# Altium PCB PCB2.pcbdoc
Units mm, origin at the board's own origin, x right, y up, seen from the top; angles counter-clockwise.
Board outline 219.08 x 148.92 mm, 2 copper layers (Top Layer, Bottom Layer); 86 components, 96 nets, 400 pads, 0 vias.
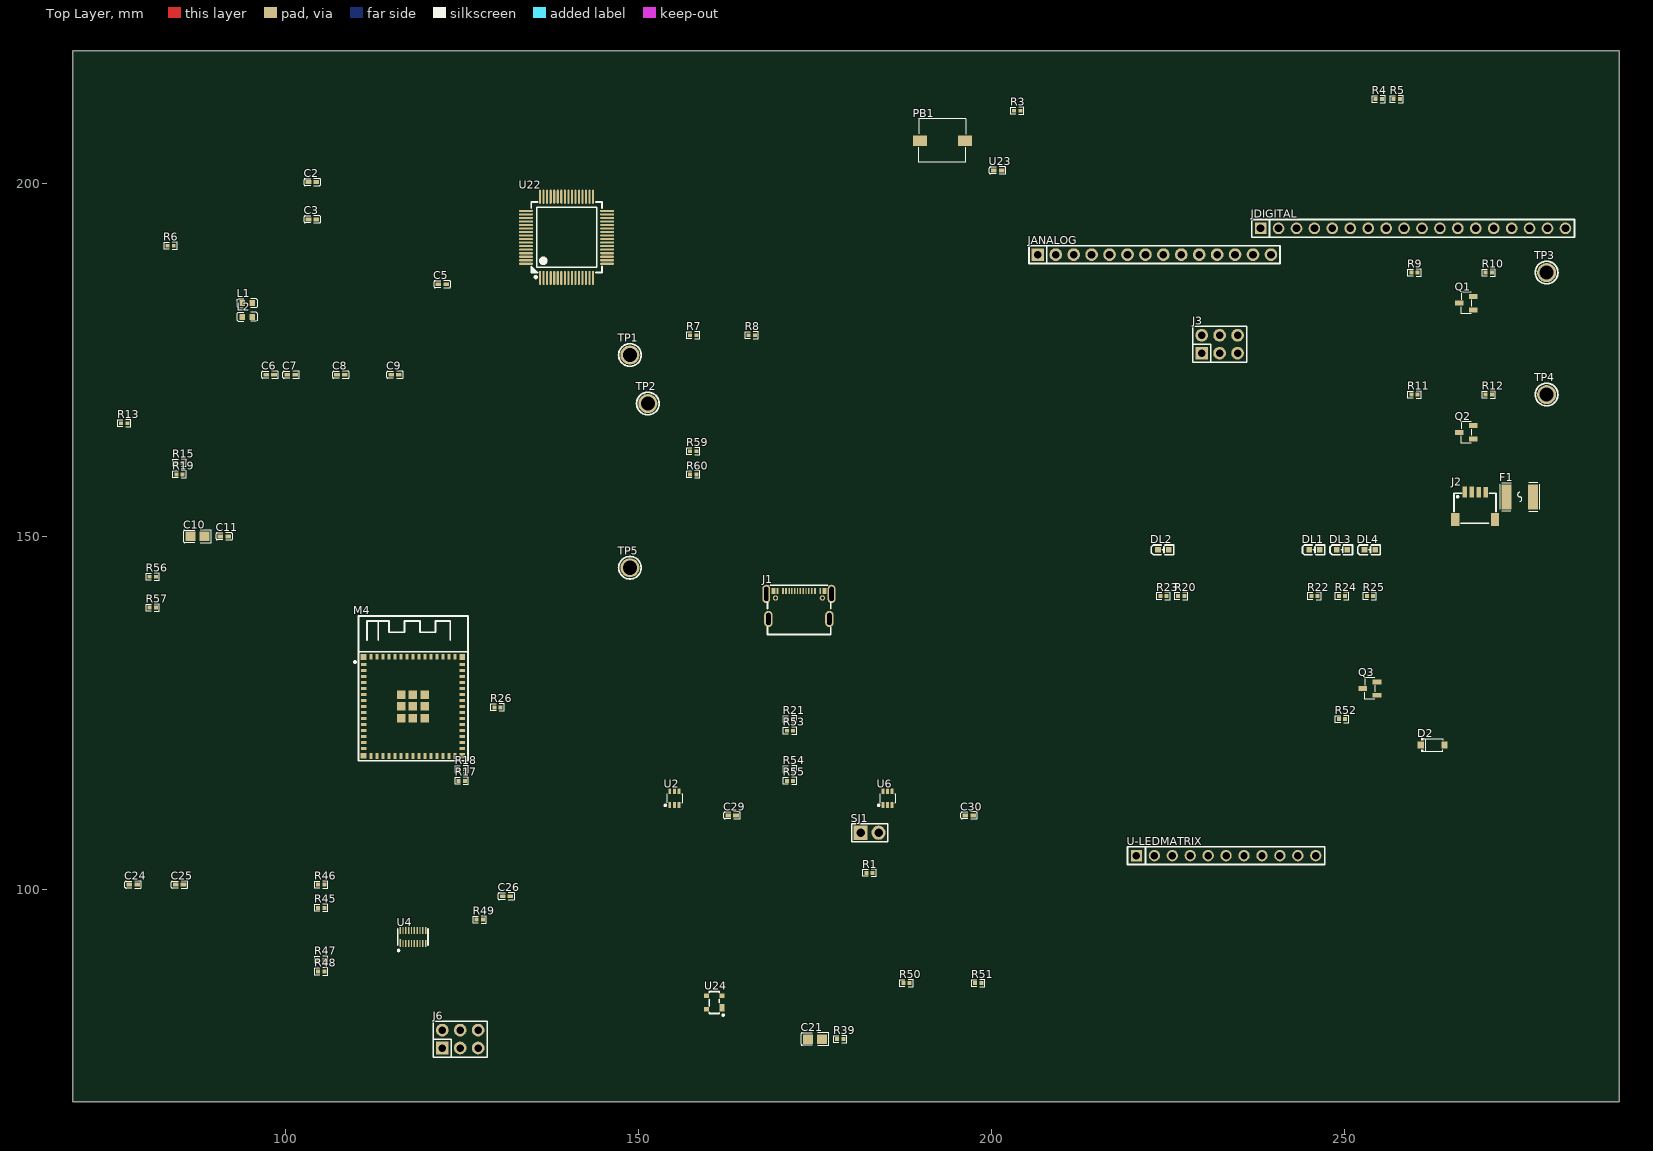
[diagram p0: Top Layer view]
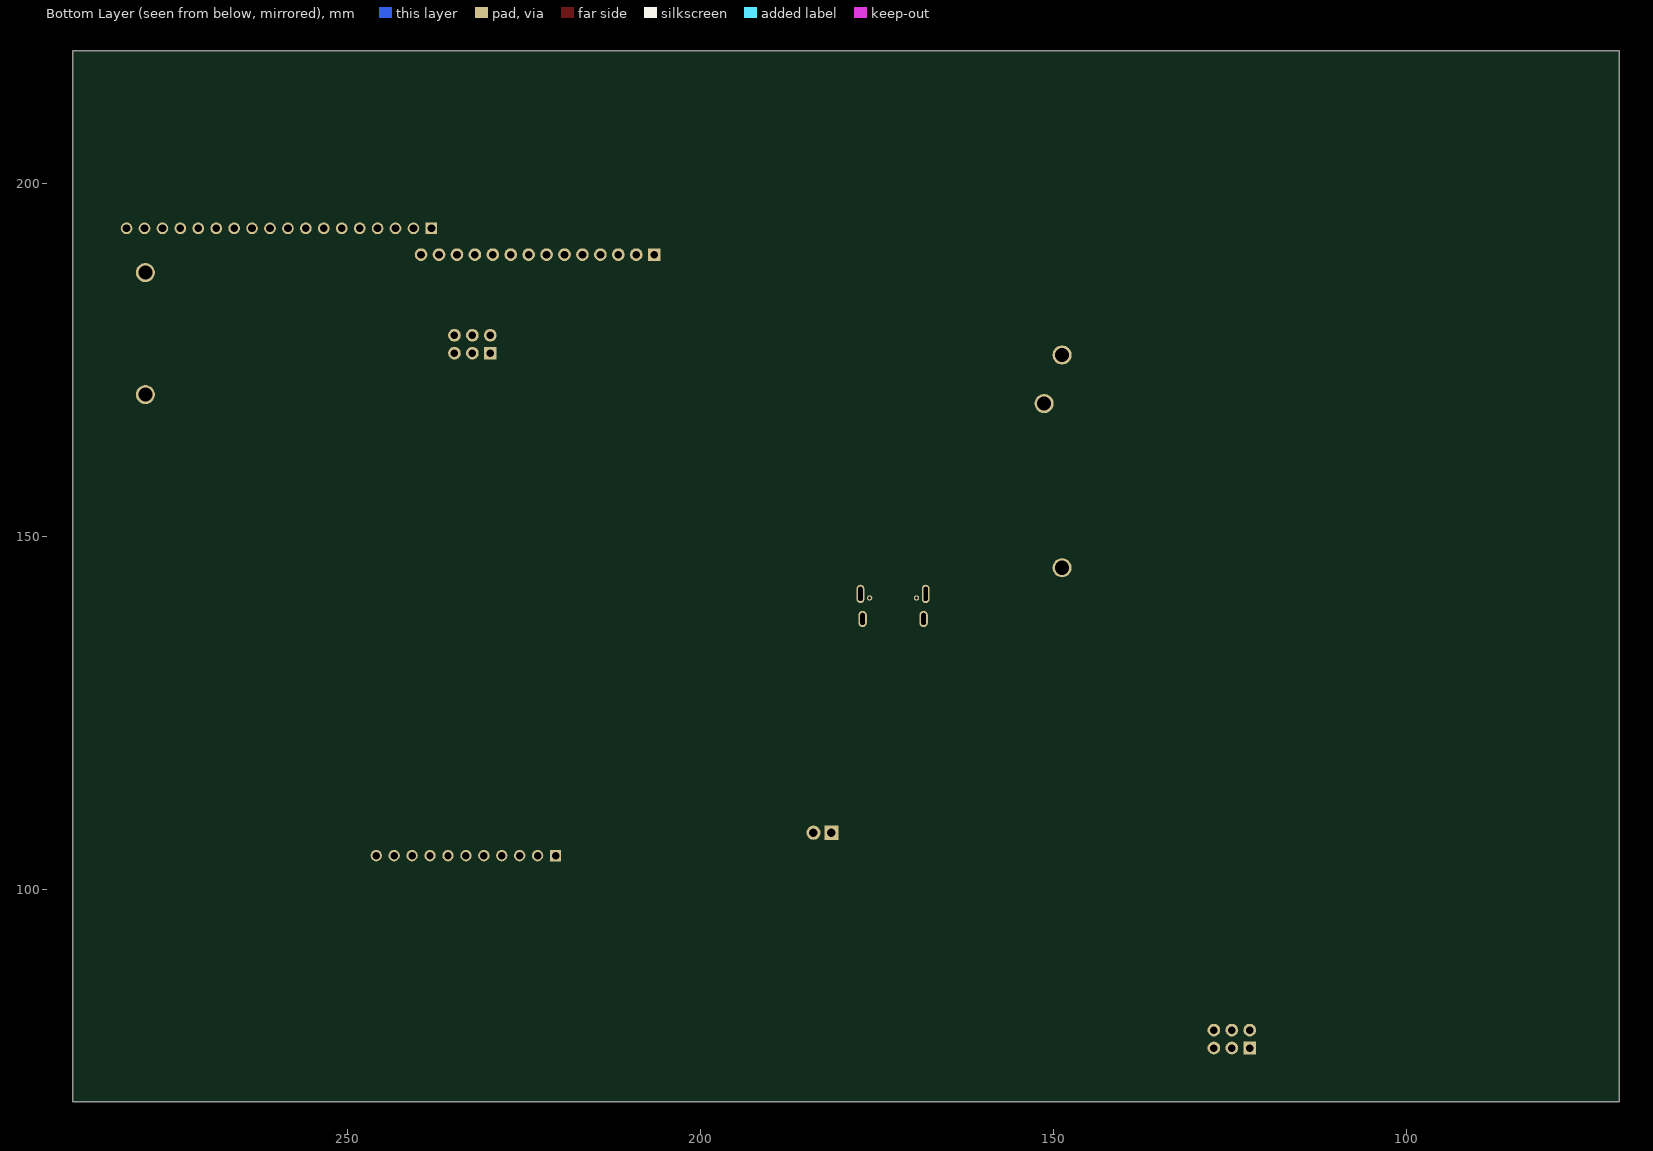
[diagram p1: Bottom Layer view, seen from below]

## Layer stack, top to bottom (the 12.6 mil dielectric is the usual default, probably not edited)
Top Layer: signal copper (thickness not stored)
Dielectric: dielectric 0.32, FR-4, Dk 4.8
Bottom Layer: signal copper (thickness not stored)

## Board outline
288.927,69.85 69.85,69.85 69.85,218.768 288.927,218.768

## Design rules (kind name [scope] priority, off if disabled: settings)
BoardOutlineClearance copperThickness1oz [All] p0: genericclearance=0.254 ignorepadtopadclearanceinfootprint=FALSE except(0: Arc-SplitContinuation Track-SplitContinuation SMDPad-SplitContinuation THPad-SplitContinuation Via-SplitContinuation Fill-SplitContinuation Poly-SplitContinuation Region-SplitContinuation Text-SplitContinuation; 0.152: Track-CutoutEdge SMDPad-CutoutEdge THPad-CutoutEdge Via-CutoutEdge Region-CutoutEdge; 0.3: Track-OutlineEdge SMDPad-OutlineEdge THPad-OutlineEdge Via-OutlineEdge Fill-OutlineEdge Region-OutlineEdge Poly-OutlineEdge Text-OutlineEdge Fill-CutoutEdge)
BoardOutlineClearance copperThickness2oz [All] p0: genericclearance=0.254 ignorepadtopadclearanceinfootprint=FALSE except(0: Arc-SplitContinuation Track-SplitContinuation SMDPad-SplitContinuation THPad-SplitContinuation Via-SplitContinuation Fill-SplitContinuation Poly-SplitContinuation Region-SplitContinuation Text-SplitContinuation; 0.152: Track-CutoutEdge SMDPad-CutoutEdge THPad-CutoutEdge Via-CutoutEdge Region-CutoutEdge; 0.3: Track-OutlineEdge SMDPad-OutlineEdge THPad-OutlineEdge Via-OutlineEdge Fill-OutlineEdge Region-OutlineEdge Poly-OutlineEdge Text-OutlineEdge Fill-CutoutEdge)
Clearance copperThickness1oz [(InNet('+4V5') OR InNet('GND') OR InNet('$1N538') OR InNet('$1N557') OR InNet('$1N850') OR InNet('$1N844') OR InNet('+3V3') OR InNet('SHIELD1') OR InNet('VUSB') OR InNet('$1N17736') OR InNet('$1N17478') OR InNet('$1N17740') OR InNet('$1N17745') OR InNet('+3V3_I2C') OR InNet('CC1') OR InNet('USB_D_P') OR InNet('USB_D_N') OR InNet('CC2') OR InNet('EXT_SCL') OR InNet('EXT_SDA') OR InNet('RESET') OR InNet('P411_SPI0_MOSI_GPT6_A') OR InNet('P102_SPI0_RSPCK_GPT2_B_CAN0_RX') OR InNet('P410_SPI0_MISO_GPT6_B') OR InNet('ESP_RXD0') OR InNet('ESP_DOWNLOAD') OR InNet('ESP_TXD0') OR InNet('ESP_IO41') OR InNet('ESP_IO42') OR InNet('P100_AN22_SCL') OR InNet('P101_AN21_SDA') OR InNet('P002_AN02_AMPO') OR InNet('P001_AN01_AMP-') OR InNet('P000_AN00_AMP+') OR InNet('P014_AN09_DAC') OR InNet('MD') OR InNet('P301_SCI2_RXD') OR InNet('P302_SCI2_TXD') OR InNet('P104_IRQ01_GPT1_B') OR InNet('P105_IRQ00_GPT1_A') OR InNet('P106_GPT0_B') OR InNet('P107_GPT0_A') OR InNet('P111_GPT3_A') OR InNet('P112_GPT3_B') OR InNet('P304_GPT7_A') OR InNet('P303_GPT7_B') OR InNet('P103_SPI0_SSL_GPT2_A_CAN0_TX') OR InNet('AREF') OR InNet('$1N548') OR InNet('$1N9257') OR InNet('ESP_IO4') OR InNet('ESP_IO5') OR InNet('ESP_IO6') OR InNet('ESP_IO7') OR InNet('ESP_IO8') OR InNet('ESP_IO9') OR InNet('ESP_N') OR InNet('ESP_P') OR InNet('ESP_MTCK') OR InNet('ESP_MTDO') OR InNet('$1N10041') OR InNet('$1N9954') OR InNet('ESP32_ENABLE') OR InNet('P400_IIC0_SCL') OR InNet('P401_IIC0_SDA') OR InNet('$1N17819') OR InNet('P408') OR InNet('$1N1751') OR InNet('$1N1642') OR InNet('$1N1620') OR InNet('P109_SCI9_TXD') OR InNet('$1N12095') OR InNet('P501_SCI1_TXD') OR InNet('$1N12097') OR InNet('P502_SCI1_RXD') OR InNet('$1N12093') OR InNet('P110_SCI9_RXD') OR InNet('$1N12091') OR InNet('$1N11720') OR InNet('RA4_P') OR InNet('RA4_N') OR InNet('$1N2290') OR InNet('$1N2029') OR InNet('P108_SWDIO') OR InNet('P300_SWCLK') OR InNet('P003') OR InNet('P004') OR InNet('P011') OR InNet('P012') OR InNet('P013') OR InNet('P015') OR InNet('P204') OR InNet('P205') OR InNet('P206') OR InNet('P212') OR InNet('P213'))] p1: gap=0.178 ignorepadtopadclearanceinfootprint=FALSE except(0.102: Track-Track; 0.152: Track-SMDPad SMDPad-SMDPad Track-THPad SMDPad-THPad THPad-THPad Track-Via SMDPad-Via THPad-Via Via-Via SMDPad-Fill THPad-Fill Via-Fill Fill-Fill Track-Region SMDPad-Region THPad-Region Via-Region Region-Region Track-Poly SMDPad-Poly THPad-Poly Via-Poly Fill-Poly Region-Poly Poly-Poly Track-Text SMDPad-Text THPad-Text Via-Text Fill-Text Region-Text Poly-Text Text-Text; 0.175: Track-Hole SMDPad-Hole THPad-Hole Via-Hole Fill-Hole Region-Hole Poly-Hole Text-Hole Sheet-Hole; 0.3: Track-Fill Fill-Region Track-Sheet SMDPad-Sheet THPad-Sheet Via-Sheet Fill-Sheet Region-Sheet Poly-Sheet Text-Sheet)
Clearance copperThickness2oz [All] p1: gap=0.178 ignorepadtopadclearanceinfootprint=FALSE except(0.152: Track-SMDPad SMDPad-SMDPad Track-THPad SMDPad-THPad THPad-THPad Track-Via SMDPad-Via THPad-Via Via-Via SMDPad-Fill THPad-Fill Via-Fill Fill-Fill Track-Region SMDPad-Region THPad-Region Via-Region Region-Region Track-Poly SMDPad-Poly THPad-Poly Via-Poly Fill-Poly Region-Poly Poly-Poly Track-Text SMDPad-Text THPad-Text Via-Text Fill-Text Region-Text Poly-Text Text-Text; 0.175: Track-Hole SMDPad-Hole THPad-Hole Via-Hole Fill-Hole Region-Hole Poly-Hole Text-Hole Sheet-Hole; 0.203: Track-Track; 0.3: Track-Fill Fill-Region Track-Sheet SMDPad-Sheet THPad-Sheet Via-Sheet Fill-Sheet Region-Sheet Poly-Sheet Text-Sheet)
DiffPairsRouting differentialPair [All] p1: maxuncoupledlength=10 minlimit=6 maxlimit=6 mostfreqgap=6 toplayer_minwidth=5 toplayer_prefwidth=10 toplayer_maxwidth=100 bottomlayer_minwidth=5 bottomlayer_prefwidth=10 bottomlayer_maxwidth=100
PasteMaskExpansion pasteMaskExpansion [All] p1: expansion=0
PlaneConnect innerPlane [All] p1: planeconnectstyle=Relief reliefexpansion=0.508 reliefentries=4 reliefconductorwidth=0.254 reliefairgap=0.254
PolygonConnect copperRegion [All] p1: connectstyle=Relief reliefentries=4 reliefconductorwidth=10 polygonreliefangle="90 Angle" airgapwidth=10
RoutingVias viaSize [All] p1: viastyle="Through Hole" holewidth=12.0078 minholewidth=11.811 maxholewidth=248.0314 width=24.0158 minwidth=19.685 maxwidth=393.7008
SolderMaskExpansion solderMaskExpansion [All] p1: useseparateexpansions=TRUE expansion=2 expansionbottom=2
Width copperThickness1oz [All] p1: maxlimit=100 minlimit=5 preferedwidth=10
Width copperThickness2oz [All] p1: maxlimit=100 minlimit=8 preferedwidth=10

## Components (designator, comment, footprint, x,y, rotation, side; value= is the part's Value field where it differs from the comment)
C2 "CL05A105KP5NNNC" C0402 103.785,200.166 r0 top
C3 "GRM155R61H104KE19D" C0402 103.785,194.881 r0 top
C5 "CL05A105KP5NNNC" C0402 122.192,185.7 r0 top
C6 "CL05A105KP5NNNC" C0402 97.806,172.866 r0 top
C7 "GRM155R61H104KE19D" C0402 100.795,172.866 r0 top
C8 "GRM155R61H104KE19D" C0402 107.821,172.866 r0 top
C9 "CL05A105KP5NNNC" C0402 115.494,172.866 r0 top
C10 "CL21A226MAQNNNE" C0805 87.53,149.976 r0 top
C11 "GRM155R61H104KE19D" C0402 91.315,149.976 r0 top
C21 "FV21X472K102ECG" C0805 175.011,78.76 r0 top
C24 "CL05A105KP5NNNC" C0402 78.414,100.642 r0 top
C25 "GRM155R61H104KE19D" C0402 84.99,100.642 r0 top
C26 "GRM155R61H104KE19D" C0402 131.309,98.993 r0 top
C29 "GRM155R61H104KE19D" C0402 163.265,110.439 r0 top
C30 "GRM155R61H104KE19D" C0402 196.847,110.439 r0 top
D2 "PMEG6020AELRX" SOD-123_L2.6-W1.7-LS3.5-RD 262.488,120.423 r0 top
DL1 "VFHL1116P-4BX3C-TR" LED-SMD_L1.6-W0.8-RD 245.747,148.073 r0 top
DL2 "VFHL1116P-4BX3C-TR" LED-SMD_L1.6-W0.8-RD 224.346,148.073 r0 top
DL3 "HSMG-C190" LED-SMD_L1.6-W0.8-R-RD 249.672,148.073 r0 top
DL4 "VFHL1116P-4BX3C-TR" LED-SMD_L1.6-W0.8-RD 253.596,148.073 r0 top
F1 "MF-MSMF050-2" F1812 274.832,155.563 r0 top
J1 "CX90B-16P" USB-C-SMD_CX90B-16P 172.721,140.261 r0 top
J2 "SM04B-SRSS-TB(LF)(SN)" CONN-SMD_4P-P1.00_SM04B-SRSS-TB-LF-SN 268.531,154.293 r0 top
J3 "PH2-06-UA" HDR-TH_6P-P2.54-V-M-R2-C3-S2.54-1 232.318,177.2 r0 top
J6 "PH2-06-UA" HDR-TH_6P-P2.54-V-M-R2-C3-S2.54-1 124.732,78.76 r0 top
JANALOG "PZ254-1-14-Z-8.5" HDR-TH_14P-P2.54-V-M 223.076,189.889 r0 top
JDIGITAL "PZ254-1-18-Z-8.5" HDR-TH_18P-P2.54-V-M 259.717,193.611 r0 top
L1 "BLM18PG471SN1D" L0603 94.56,183.023 r0 top
L2 "BLM18PG471SN1D" L0603 94.56,181.069 r0 top
M4 "ESP32-S3-MINI-1-N8" BULETM-SMD_ESP32-S3-MINI-1-N8 118.034,125.879 r0 top
PB1 "SPEH130103" SW-SMD_L6.0-W6.0-LS6.6 193.037,206.043 r0 top
Q1 "2N7002KT1G" SOT-23-3_L2.9-W1.3-P1.90-LS2.4-BR 267.261,183.023 r0 top
Q2 "2N7002KT1G" SOT-23-3_L2.9-W1.3-P1.90-LS2.4-BR 267.261,164.723 r0 top
Q3 "2N7002KT1G" SOT-23-3_L2.9-W1.3-P1.90-LS2.4-BR 253.596,128.419 r0 top
R1 "CRCW0402100KFKEDC" R0402 182.734,102.292 r0 top
R3 "CRCW0402100KFKEDC" R0402 203.648,210.27 r0 top
R4 "RC0402FR-075K1L" R0402 254.866,211.919 r0 top
R5 "RC0402FR-075K1L" R0402 257.407,211.919 r0 top
R6 "RC0402FR-075K1L" R0402 83.72,191.159 r0 top
R7 "RC0402FR-075K1L" R0402 157.755,178.47 r0 top
R8 "RC0402FR-075K1L" R0402 166.031,178.47 r0 top
R9 "RC0402FR-075K1L" R0402 259.948,187.349 r0 top
R10 "RC0402FR-075K1L" R0402 270.441,187.349 r0 top
R11 "RC0402FR-075K1L" R0402 259.948,170.065 r0 top
R12 "RC0402FR-075K1L" R0402 270.441,170.065 r0 top
R13 "RC0402FR-075K1L" R0402 77.144,165.993 r0 top
R15 "RC0402FR-075K1L" R0402 84.99,160.396 r0 top
R17 "CRCW04020000Z0EDC" R0402 124.957,115.328 r0 top
R18 "CRCW04020000Z0EDC" R0402 124.957,116.978 r0 top
R19 "RC0402FR-075K1L" R0402 84.99,158.746 r0 top
R20 "CRCW0402330RJNED" R0402 226.886,141.531 r0 top
R21 "CRCW04020000Z0EDC" R0402 171.451,124.093 r0 top
R22 "CRCW0402330RJNED" R0402 245.747,141.531 r0 top
R23 "CRCW0402330RJNED" R0402 224.346,141.531 r0 top
R24 "CRCW0402330RJNED" R0402 249.672,141.531 r0 top
R25 "CRCW0402330RJNED" R0402 253.596,141.531 r0 top
R26 "ERA2AEB104X" R0402 130.039,125.742 r0 top
R39 "CRCW04021M00FKED" R0402 178.571,78.76 r0 top
R45 "CRCW04020000Z0EDC" R0402 105.055,97.343 r0 top
R46 "CRCW04020000Z0EDC" R0402 105.055,100.642 r0 top
R47 "CRCW04020000Z0EDC" R0402 105.055,89.985 r0 top
R48 "CRCW04020000Z0EDC" R0402 105.055,88.335 r0 top
R49 "ERA2AEB104X" R0402 127.498,95.693 r0 top
R50 "RC0402FR-075K1L" R0402 187.957,86.686 r0 top
R51 "RC0402FR-075K1L" R0402 198.117,86.686 r0 top
R52 "ERA2AEB104X" R0402 249.672,124.093 r0 top
R53 "CRCW04020000Z0EDC" R0402 171.451,122.443 r0 top
R54 "CRCW04020000Z0EDC" R0402 171.451,116.978 r0 top
R55 "CRCW04020000Z0EDC" R0402 171.451,115.328 r0 top
R56 "ERA2AEB104X" R0402 81.18,144.263 r0 top
R57 "ERA2AEB104X" R0402 81.18,139.881 r0 top
R59 "ERA2AEB104X" R0402 157.755,162.046 r0 top
R60 "RT0402BRD0713K7L" R0402 157.755,158.746 r0 top
SJ1 "IOVDD_1797" HDR-TH_2P-P2.54-V-M 182.734,107.992 r0 top
TP1 "LOVE" TESTPOINT-TH_BD3.2 148.78,175.668 r0 top
TP2 "MD" TESTPOINT-TH_BD3.2 151.32,168.795 r0 top
TP3 "IIC0_SCL" TESTPOINT-TH_BD3.2 278.642,187.349 r0 top
TP4 "IIC0_SDA" TESTPOINT-TH_BD3.2 278.642,170.065 r0 top
TP5 "VUBS_CONN" TESTPOINT-TH_BD3.2 148.78,145.533 r0 top
U2 "TPNLASB3157DFT2G" SOT-363-6_L2.0-W1.3-P0.65-LS2.3-BL 155.071,112.883 r0 top
U4 "TXB0108DQSR" SON-20_L4.0-W2.0-P0.40-BL 118.034,93.219 r0 top
U6 "TPNLASB3157DFT2G" SOT-363-6_L2.0-W1.3-P0.65-LS2.3-BL 185.274,112.883 r0 top
U22 "R7FA4M1AB3CFM#AA0" LQFP-64_L10.0-W10.0-P0.50-LS12.0-BL 139.803,192.341 r0 top
U23 "CC0402KRX7R6BB474" C0402 200.883,201.815 r0 top
U24 "PRTR5V0U2X-ES" SOT-143_L2.9-W1.3-P1.92-LS2.3-BR 160.725,83.934 r0 top
U-LEDMATRIX "HB-PH3-254111PB2GOP" HDR-TH_11P-P2.54-V-M 233.236,104.744 r0 top

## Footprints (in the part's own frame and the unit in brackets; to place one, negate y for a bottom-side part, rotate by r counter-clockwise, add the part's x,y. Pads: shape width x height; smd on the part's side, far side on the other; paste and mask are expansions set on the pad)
BULETM-SMD_ESP32-S3-MINI-1-N8 [mm]
  rect 0.8x0.4 smd: 1(-6.975,5.95) 2(-6.975,5.1) 3(-6.975,4.25) 4(-6.975,3.4) 5(-6.975,2.55) 6(-6.975,1.7) 7(-6.975,0.85) 8(-6.975,0) 9(-6.975,-0.85) 10(-6.975,-1.7) 11(-6.975,-2.55) 12(-6.975,-3.4) 13(-6.975,-4.25) 14(-6.975,-5.1) 15(-6.975,-5.95) 31(6.975,-5.95) 32(6.975,-5.1) 33(6.975,-4.25) 34(6.975,-3.4) 35(6.975,-2.55) 36(6.975,-1.7) 37(6.975,-0.85) 38(6.975,0) 39(6.975,0.85) 40(6.975,1.7) 41(6.975,2.55) 42(6.975,3.4) 43(6.975,4.25) 44(6.975,5.1) 45(6.975,5.95)
  rect 0.4x0.8 smd: 16(-5.95,-7.025) 17(-5.1,-7.025) 18(-4.25,-7.025) 19(-3.4,-7.025) 20(-2.55,-7.025) 21(-1.7,-7.025) 22(-0.85,-7.025) 23(0,-7.025) 24(0.85,-7.025) 25(1.7,-7.025) 26(2.55,-7.025) 27(3.4,-7.025) 28(4.25,-7.025) 29(5.1,-7.025) 30(5.95,-7.025) 46(5.95,7.025) 47(5.1,7.025) 48(4.25,7.025) 49(3.4,7.025) 50(2.55,7.025) 51(1.7,7.025) 52(0.85,7.025) 53(0,7.025) 54(-0.85,7.025) 55(-1.7,7.025) 56(-2.55,7.025) 57(-3.4,7.025) 58(-4.25,7.025) 59(-5.1,7.025) 60(-5.95,7.025)
  rect 0.8x0.8 smd: GND(-7,-7) GND(-7,7) GND(7,-7) GND(7,7)
  rect 1.2x1.2 smd: GND(-1.65,-1.65) GND(-1.65,0) GND(-1.65,1.65) GND(0,-1.65) GND(0,0) GND(0,1.65) GND(1.65,-1.65) GND(1.65,0) GND(1.65,1.65)
  silkscreen extent -8.34,-7.7 7.8,12.8
C0402 [mm]
  rect 0.79x0.54 smd: 1(-0.545,0) 2(0.545,0)
  silkscreen extent -1.17,-0.5 1.17,0.5
C0805 [mm]
  rect 1.41x1.35 smd: 1(-1,0) 2(1,0)
  silkscreen extent -1.96,-0.9 1.96,0.9
CONN-SMD_4P-P1.00_SM04B-SRSS-TB-LF-SN [mm]
  rect 0.6x1.55 smd: 1(-1.5,1.938) 2(-0.5,1.938) 3(0.5,1.938) 4(1.5,1.938)
  rect 1.2x1.8 smd: 5(2.8,-1.938) 6(-2.8,-1.938)
  silkscreen extent -3.02,-2.46 2.96,1.8
F1812 [mm]
  rect 1.407x3.499 smd: 1(-1.853,0) 2(1.853,0)
  silkscreen extent -2.79,-2.03 2.79,2.03
HDR-TH_2P-P2.54-V-M [mm]
  rect 2x2 hole 1.2: 1(-1.27,0)
  round 2 hole 1.2: 2(1.27,0)
  silkscreen extent -2.54,-1.27 2.54,1.27
HDR-TH_6P-P2.54-V-M-R2-C3-S2.54-1 [mm]
  rect 1.8x1.8 hole 1.05: 1(-2.54,-1.27)
  round 1.8 hole 1.05: 2(-2.54,1.27) 3(0,-1.27) 4(0,1.27) 5(2.54,-1.27) 6(2.54,1.27)
  silkscreen extent -3.81,-2.54 3.81,2.54
HDR-TH_11P-P2.54-V-M [mm]
  rect 1.6x1.6 hole 1.05: 1(-12.7,0)
  round 1.6 hole 1.05: 2(-10.16,0) 3(-7.62,0) 4(-5.08,0) 5(-2.54,0) 6(0,0) 7(2.54,0) 8(5.08,0) 9(7.62,0) 10(10.16,0) 11(12.7,0)
  silkscreen extent -13.97,-1.25 13.97,1.25
HDR-TH_14P-P2.54-V-M [mm]
  rect 1.8x1.8 hole 1.1: 1(-16.51,0)
  round 1.8 hole 1.1: 2(-13.97,0) 3(-11.43,0) 4(-8.89,0) 5(-6.35,0) 6(-3.81,0) 7(-1.27,0) 8(1.27,0) 9(3.81,0) 10(6.35,0) 11(8.89,0) 12(11.43,0) 13(13.97,0) 14(16.51,0)
  silkscreen extent -17.78,-1.25 17.78,1.25
HDR-TH_18P-P2.54-V-M [mm]
  rect 1.65x1.6 hole 1.1: 1(-21.59,0)
  round 1.65 hole 1.1: 2(-19.05,0) 3(-16.51,0) 4(-13.97,0) 5(-11.43,0) 6(-8.89,0) 7(-6.35,0) 8(-3.81,0) 9(-1.27,0) 10(1.27,0) 11(3.81,0) 12(6.35,0) 13(8.89,0) 14(11.43,0) 15(13.97,0) 16(16.51,0) 17(19.05,0) 18(21.59,0)
  silkscreen extent -22.86,-1.25 22.86,1.25
L0603 [mm]
  rect 0.8x0.864 smd: 1(-0.7,0) 2(0.7,0)
  silkscreen extent -1.42,-0.65 1.42,0.65
LED-SMD_L1.6-W0.8-R-RD [mm]
  rect 0.8x0.8 smd: 1(0.75,0) 2(-0.75,0)
  silkscreen extent -1.7,-0.7 1.47,0.7
LED-SMD_L1.6-W0.8-RD [mm]
  rect 0.8x0.8 smd: 1(-0.75,0) 2(0.75,0)
  silkscreen extent -1.7,-0.7 1.47,0.7
LQFP-64_L10.0-W10.0-P0.50-LS12.0-BL [mm]
  oval 0.3x2 smd: 1(-3.75,-5.75) 2(-3.25,-5.75) 3(-2.75,-5.75) 4(-2.25,-5.75) 5(-1.75,-5.75) 6(-1.25,-5.75) 7(-0.75,-5.75) 8(-0.25,-5.75) 9(0.25,-5.75) 10(0.75,-5.75) 11(1.25,-5.75) 12(1.75,-5.75) 13(2.25,-5.75) 14(2.75,-5.75) 15(3.25,-5.75) 16(3.75,-5.75) 33(3.75,5.75) 34(3.25,5.75) 35(2.75,5.75) 36(2.25,5.75) 37(1.75,5.75) 38(1.25,5.75) 39(0.75,5.75) 40(0.25,5.75) 41(-0.25,5.75) 42(-0.75,5.75) 43(-1.25,5.75) 44(-1.75,5.75) 45(-2.25,5.75) 46(-2.75,5.75) 47(-3.25,5.75) 48(-3.75,5.75)
  oval 2x0.3 smd: 17(5.75,-3.75) 18(5.75,-3.25) 19(5.75,-2.75) 20(5.75,-2.25) 21(5.75,-1.75) 22(5.75,-1.25) 23(5.75,-0.75) 24(5.75,-0.25) 25(5.75,0.25) 26(5.75,0.75) 27(5.75,1.25) 28(5.75,1.75) 29(5.75,2.25) 30(5.75,2.75) 31(5.75,3.25) 32(5.75,3.75) 49(-5.75,3.75) 50(-5.75,3.25) 51(-5.75,2.75) 52(-5.75,2.25) 53(-5.75,1.75) 54(-5.75,1.25) 55(-5.75,0.75) 56(-5.75,0.25) 57(-5.75,-0.25) 58(-5.75,-0.75) 59(-5.75,-1.25) 60(-5.75,-1.75) 61(-5.75,-2.25) 62(-5.75,-2.75) 63(-5.75,-3.25) 64(-5.75,-3.75)
  silkscreen extent -5,-5.79 5,5
R0402 [mm]
  rect 0.566x0.54 smd: 1(-0.433,0) 2(0.433,0)
  silkscreen extent -0.94,-0.5 0.94,0.5
SOD-123_L2.6-W1.7-LS3.5-RD [mm]
  rect 0.9x1 smd: 1(-1.692,0) 2(1.692,0)
  silkscreen extent -1.63,-0.94 1.41,0.94
SON-20_L4.0-W2.0-P0.40-BL [mm]
  rect 0.2x1.1 smd: 1(-1.8,-0.85)
  rect 0.2x1 smd: 2(-1.4,-0.9) 3(-1,-0.9) 4(-0.6,-0.9) 5(-0.2,-0.9) 6(0.2,-0.9) 7(0.6,-0.9) 8(1,-0.9) 9(1.4,-0.9) 10(1.8,-0.9) 11(1.8,0.9) 12(1.4,0.9) 13(1,0.9) 14(0.6,0.9) 15(0.2,0.9) 16(-0.2,0.9) 17(-0.6,0.9) 18(-1,0.9) 19(-1.4,0.9) 20(-1.8,0.9)
  silkscreen extent -2.16,-2.03 2.16,1.14
SOT-23-3_L2.9-W1.3-P1.90-LS2.4-BR [mm]
  rect 1.25x0.7 smd: 1(1,-0.95) 2(1,0.95) 3(-1,0)
  silkscreen extent -0.73,-1.53 0.73,1.53
SOT-143_L2.9-W1.3-P1.92-LS2.3-BR [mm]
  rect 0.7x1.1 smd: 1(1.1,-0.75)
  rect 0.7x0.6 smd: 2(1.1,0.95) 3(-1.1,0.95) 4(-1.1,-0.95)
  silkscreen extent -0.7,-1.91 1.4,1.55
SOT-363-6_L2.0-W1.3-P0.65-LS2.3-BL [mm]
  rect 0.4x0.8 smd: 1(-0.65,-0.97) 2(0,-0.97) 3(0.65,-0.97) 4(0.65,0.97) 5(0,0.97) 6(-0.65,0.97)
  silkscreen extent -1.4,-1.14 1.1,0.65
SW-SMD_L6.0-W6.0-LS6.6 [mm]
  rect 1.985x1.512 smd: 1(-3.193,0) 2(3.193,0)
  silkscreen extent -3.33,-3.08 3.33,3.08
TESTPOINT-TH_BD3.2 [mm]
  round 2.7 hole 2: 1(0,0)
  silkscreen extent -1.6,-1.6 1.6,1.6
USB-C-SMD_CX90B-16P [mm]
  oval 1.1x2.6 hole 0.6 slot 2 at 90 deg: 0(-4.62,1.563) 0(4.62,1.563)
  oval 1.2x2.3 hole 0.6 slot 1.7 at 90 deg: 1(-4.32,-1.987) 1(4.32,-1.987)
  round 0.75 hole 0.45: 2(-3.32,0.988) 3(3.32,0.988)
  rect 0.57x0.85 smd: A1(-3.635,1.987) A12(3.635,1.987)
  rect 0.25x0.85 smd: A4(-2.275,1.987) A9(2.275,1.987) B1(3.025,1.987) B4(1.825,1.987) B9(-1.825,1.987) B12(-3.025,1.987)
  rect 0.2x0.85 smd: A5(-1.4,1.987) A6(-0.6,1.987) A7(0.6,1.987) A8(1.4,1.987) B5(1,1.987) B6(0.2,1.987) B7(-0.2,1.987) B8(-1,1.987)
  silkscreen extent -4.45,-4.19 4.5,2.8

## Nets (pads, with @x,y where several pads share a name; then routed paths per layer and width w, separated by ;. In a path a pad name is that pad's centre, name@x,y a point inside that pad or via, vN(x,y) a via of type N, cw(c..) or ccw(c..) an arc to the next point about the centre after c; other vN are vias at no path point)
$1N538: C5.2 U22.20
$1N548: L1.2 U22.59
$1N557: C6.2 C7.2 L2.2 U22.56
$1N844: C9.2 U22.5
$1N850: C8.2 U22.4
$1N1620: R15.1 R19.2
$1N1642: R13.1 R15.2 U22.16
$1N1751: R7.1 U22.27
$1N2029: TP1.1 U22.38
$1N2290: R59.1 R60.2 U22.49
$1N9257: M4.7 R56.1 R57.2
$1N9954: M4.40 R18.1
$1N10041: M4.39 R17.1
$1N11720: R49.1 U4.6
$1N12091: R48.2 U4.11
$1N12093: R47.2 U4.12
$1N12095: R45.2 U4.18
$1N12097: R46.2 U4.19
$1N17478: DL2.1 R20.2 R23.2
$1N17736: DL1.1 R22.2
$1N17740: DL3.2 R24.2
$1N17745: DL4.1 R25.2
$1N17819: Q3.3 R25.1
+3V3: C10.2 C11.2 C26.2 DL2.2 F1.2 JANALOG.4 M4.3 R26.1 R49.2 R56.2 U4.5
+3V3_I2C: F1.1 J2.2 Q1.1 Q2.1 R9.2 R11.2
+4V5: C2.2 C3.2 C24.2 C25.2 C29.2 C30.2 D2.1 DL1.2 DL3.1 DL4.2 J3.2 JANALOG.2 JANALOG.5 L2.1 R3.2 R4.2 R5.2 R6.2 R7.2 R8.2 R10.2 R12.2 R13.2 R59.2 SJ1.1 U2.5 U4.16 U6.5 U22.11 U22.21 U22.39
AREF: JDIGITAL.16 L1.1 R6.1
CC1: J1.A5 R50.2
CC2: J1.B5 R51.2
ESP32_ENABLE: M4.45 R26.2
ESP_DOWNLOAD: J6.4 M4.4
ESP_IO4: M4.8 U4.1
ESP_IO5: M4.9 U4.2
ESP_IO6: M4.10 U4.3
ESP_IO7: M4.11 U4.4
ESP_IO8: M4.12 U4.7
ESP_IO9: M4.13 U4.8
ESP_IO41: J6.2 M4.37
ESP_IO42: J6.1 M4.38
ESP_MTCK: M4.35
ESP_MTDO: M4.36
ESP_N: M4.23 R53.2 U6.3
ESP_P: M4.24 R21.2 U2.3
ESP_RXD0: J6.5 R18.2 U4.10
ESP_TXD0: J6.3 R17.2 R20.1 R23.1 U4.9
EXT_SCL: J2.4 Q1.2 R9.1
EXT_SDA: J2.3 Q2.2 R11.1
GND: C2.1 C3.1 C5.1 C6.1 C7.1 C8.1 C9.1 C10.1 C11.1 C21.1 C24.1 C25.1 C26.1 C29.1 C30.1 J1.A1 J1.A12 J1.B1 J1.B12 J2.1 J2.5 J2.6 J3.6 J6.6 JANALOG.6 JANALOG.7 JDIGITAL.15 M4.1 M4.2 M4.42 M4.43 M4.46 M4.47 M4.48 M4.49 M4.50 M4.51 M4.52 M4.53 M4.54 M4.55 M4.56 M4.57 M4.58 M4.59 M4.60 M4.GND PB1.1 Q3.2 R1.1 R19.1 R24.1 R39.1 R50.1 R51.1 R52.1 R57.1 R60.1 U2.2 U4.15 U6.2 U22.8 U22.17 U22.40 U22.57 U23.1
MD: JANALOG.1 R8.1 TP2.1 U4.13 U22.26
P000_AN00_AMP+: JANALOG.10 U22.64
P001_AN01_AMP-: JANALOG.11 U22.63
P002_AN02_AMPO: JANALOG.12 U22.62
P003: U22.61 U-LEDMATRIX.1
P004: U22.60 U-LEDMATRIX.2
P011: U22.58 U-LEDMATRIX.3
P012: U22.55 U-LEDMATRIX.4
P013: U22.54 U-LEDMATRIX.5
P014_AN09_DAC: JANALOG.9 U22.53
P015: U22.52 U-LEDMATRIX.6
P100_AN22_SCL: JANALOG.14 JDIGITAL.18 R4.1 U22.48
P101_AN21_SDA: JANALOG.13 JDIGITAL.17 R5.1 U22.47
P102_SPI0_RSPCK_GPT2_B_CAN0_RX: J3.3 JDIGITAL.14 Q3.1 R52.2 U22.46
P103_SPI0_SSL_GPT2_A_CAN0_TX: JDIGITAL.11 U22.45
P104_IRQ01_GPT1_B: JDIGITAL.3 U22.44
P105_IRQ00_GPT1_A: JDIGITAL.4 U22.43
P106_GPT0_B: JDIGITAL.5 U22.42
P107_GPT0_A: JDIGITAL.6 U22.41
P108_SWDIO: U4.14 U22.32
P109_SCI9_TXD: R22.1 R48.1 U22.34
P110_SCI9_RXD: R47.1 U22.35
P111_GPT3_A: JDIGITAL.7 U22.36
P112_GPT3_B: JDIGITAL.8 U22.37
P204: U22.24 U-LEDMATRIX.7
P205: U22.23 U-LEDMATRIX.8
P206: U22.22 U-LEDMATRIX.9
P212: U22.10 U-LEDMATRIX.10
P213: U22.9 U-LEDMATRIX.11
P300_SWCLK: U4.17 U22.33
P301_SCI2_RXD: JDIGITAL.1 U22.31
P302_SCI2_TXD: JDIGITAL.2 U22.30
P303_GPT7_B: JDIGITAL.10 U22.29
P304_GPT7_A: JDIGITAL.9 U22.28
P400_IIC0_SCL: Q1.3 R10.1 TP3.1 U22.1
P401_IIC0_SDA: Q2.3 R12.1 TP4.1 U22.2
P408: R1.2 SJ1.2 U2.6 U6.6 U22.15
P410_SPI0_MISO_GPT6_B: J3.1 JDIGITAL.13 U22.13
P411_SPI0_MOSI_GPT6_A: J3.4 JDIGITAL.12 U22.12
P501_SCI1_TXD: R45.1 U22.50
P502_SCI1_RXD: R46.1 U22.51
RA4_N: R55.2 U6.1 U22.18
RA4_P: R54.2 U2.1 U22.19
RESET: J3.5 JANALOG.3 PB1.2 R3.1 U4.20 U22.25 U23.2
SHIELD1: C21.2 R39.2 U24.1
USB_D_N: J1.A7 J1.B7 R53.1 R55.1 U6.4 U24.3
USB_D_P: J1.A6 J1.B6 R21.1 R54.1 U2.4 U24.2
VUSB: D2.2 J1.A4 J1.A9 J1.B4 J1.B9 JANALOG.8 TP5.1 U24.4
pads on no net: J1.0 J1.1 J1.2 J1.3 J1.A8 J1.B8 M4.5 M4.6 M4.14 M4.15 M4.16 M4.17 M4.18 M4.19 M4.20 M4.21 M4.22 M4.25 M4.26 M4.27 M4.28 M4.29 M4.30 M4.31 M4.32 M4.33 M4.34 M4.41 M4.44 U22.3 U22.6 U22.7 U22.14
